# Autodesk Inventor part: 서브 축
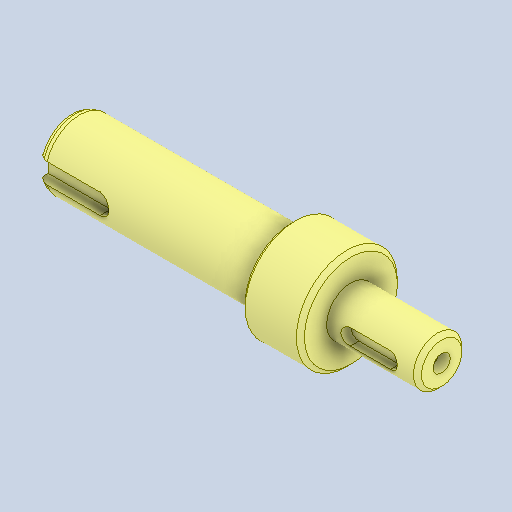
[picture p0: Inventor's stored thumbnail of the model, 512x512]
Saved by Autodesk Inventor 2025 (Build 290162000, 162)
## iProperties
Created: 2026-07
Part Number: 서브 축
Material: 강철, 탄소
Document SubType Name: Modeling
Designer: KDI
Density: 7.85 g/cm^3
Appearance: 기본값
Author: jhkim
Revision Number: 1
Sending System: Autodesk Inventor 2027
Preprocessor: ST-DEVELOPER v20.1
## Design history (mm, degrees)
feature "솔리드1"
node "솔리드2"
